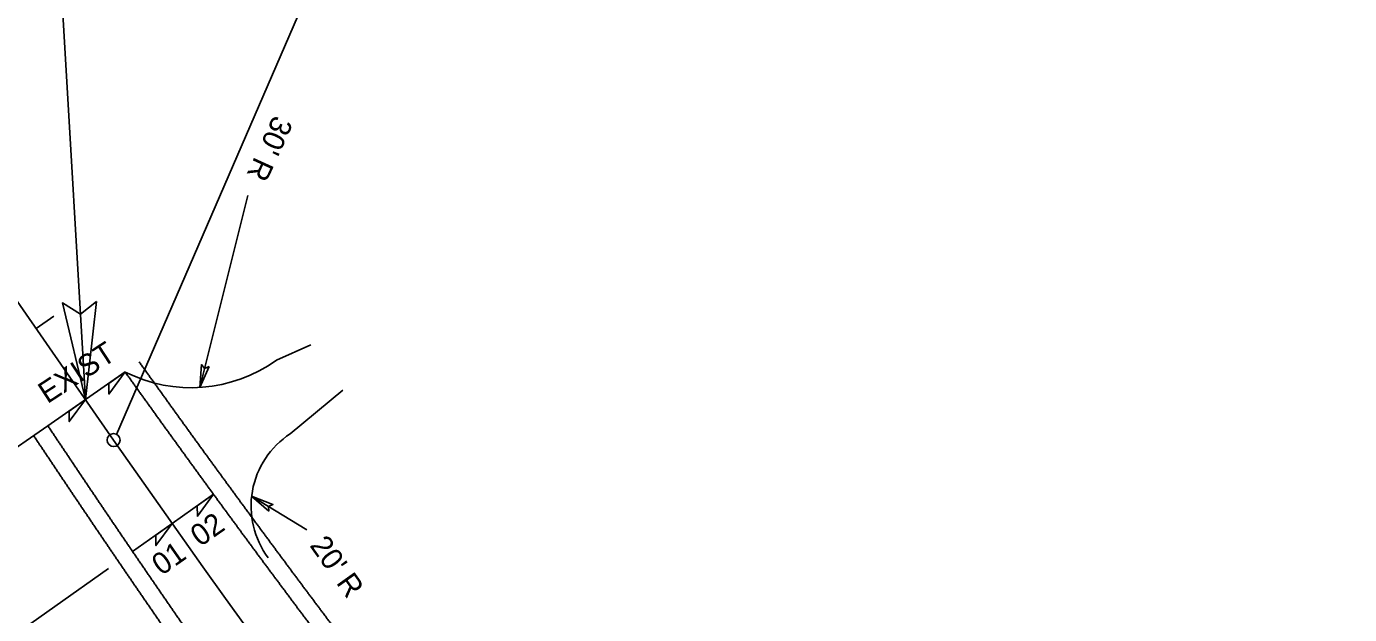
# Model space of a CAD drawing. Extents: x 1778969 to 1790720, y 807089 to 817794.
# Drawn here: x 1781813.6 to 1782119.6, y 815027.8 to 815163.8 of the extents above; entities that cross this region are included whole.
import ezdxf

# ---------------------------------------------------------------- set-up
doc = ezdxf.new("R2010")
doc.units = 0
for name, color, linetype in [('Prop Dimension', 7, 'Continuous'), ('Prop Dimension Text', 7, 'Continuous'), ('Prop EOT', 7, 'Continuous'), ('Prop Horizontal Alignment', 7, 'Continuous'), ('Prop Horizontal Alignment Station Label', 7, 'Continuous'), ('Prop Horizontal Alignment Tick Small', 7, 'Continuous'), ('Prop Paved Shoulder', 7, 'Continuous'), ('Prop Superelevation  Arrow CELL', 7, 'Continuous'), ('Prop Superelevation Label', 7, 'Continuous'), ('Prop Terminator CELL', 7, 'Continuous')]:
    doc.layers.add(name, color=color, linetype=linetype)

msp = doc.modelspace()

# ---------------------------------------------------------------- linework, layer by layer
at = {"layer": 'Prop Dimension'}
for p, q in [((1781864.83, 815124.76), (1781853.71, 815080.33)), ((1781818.55, 815071.48), (1781686.85, 814979.95)), ((1781865.7, 815055.15), (1781878.45, 815047.43)), ((1781832.62, 815038.46), (1781781.53, 815002.33))]:
    msp.add_line(p, q, dxfattribs=at)
at = {"layer": 'Prop EOT'}
for p, q in [((1781871.45, 815086.65), (1781879.41, 815090.18)), ((1781836.43, 815083.91), (1781818.55, 815071.48)), ((1781874.63, 815069.62), (1781886.8, 815079.72))]:
    msp.add_line(p, q, dxfattribs=at)
for centre, radius, start, end in [((1781851.67, 815114.12), 33.85, 243.2689, 305.749), ((1781885.57, 815052.87), 20, 123.1508, 216.6578)]:
    msp.add_arc(centre, radius, start, end, dxfattribs=at)
for points in [[(1781836.43, 815083.91), (1781837, 815083.11), (1781837.58, 815082.32), (1781838.15, 815081.52), (1781838.72, 815080.73), (1781839.29, 815079.93), (1781839.86, 815079.13), (1781840.44, 815078.34), (1781841.01, 815077.54), (1781841.58, 815076.75), (1781842.15, 815075.95), (1781842.72, 815075.16), (1781843.29, 815074.36), (1781843.86, 815073.57), (1781844.43, 815072.78), (1781845, 815071.98), (1781845.57, 815071.19), (1781846.15, 815070.4), (1781846.72, 815069.61), (1781847.29, 815068.82), (1781847.86, 815068.03), (1781848.43, 815067.24), (1781849, 815066.45), (1781849.58, 815065.65), (1781850.15, 815064.86), (1781850.72, 815064.07), (1781851.29, 815063.28), (1781851.87, 815062.5), (1781852.44, 815061.71), (1781853.02, 815060.92), (1781853.59, 815060.13), (1781854.17, 815059.34), (1781854.74, 815058.55), (1781855.31, 815057.76), (1781855.89, 815056.97), (1781856.47, 815056.18), (1781857.04, 815055.4), (1781857.62, 815054.61), (1781858.19, 815053.82), (1781858.77, 815053.03), (1781859.35, 815052.25), (1781859.93, 815051.46), (1781860.5, 815050.67), (1781861.08, 815049.89), (1781861.66, 815049.1), (1781862.24, 815048.32), (1781862.81, 815047.53), (1781863.39, 815046.74), (1781863.97, 815045.96), (1781864.55, 815045.17), (1781865.13, 815044.39), (1781865.71, 815043.6), (1781866.29, 815042.82), (1781866.87, 815042.03), (1781867.45, 815041.25), (1781868.03, 815040.47), (1781868.61, 815039.68), (1781869.2, 815038.9), (1781869.78, 815038.11), (1781870.36, 815037.33), (1781870.94, 815036.55), (1781871.52, 815035.77), (1781872.11, 815034.98), (1781872.69, 815034.2), (1781873.27, 815033.42), (1781873.86, 815032.64), (1781874.44, 815031.85), (1781875.02, 815031.07), (1781875.61, 815030.29), (1781876.19, 815029.51), (1781876.78, 815028.73), (1781877.36, 815027.95), (1781877.95, 815027.17), (1781878.53, 815026.39), (1781879.12, 815025.61)], [(1781818.55, 815071.48), (1781819.1, 815070.67), (1781819.64, 815069.85), (1781820.19, 815069.04), (1781820.73, 815068.22), (1781821.28, 815067.41), (1781821.82, 815066.6), (1781822.37, 815065.78), (1781822.92, 815064.97), (1781823.46, 815064.15), (1781824.01, 815063.34), (1781824.55, 815062.53), (1781825.1, 815061.71), (1781825.65, 815060.89), (1781826.19, 815060.08), (1781826.74, 815059.26), (1781827.29, 815058.45), (1781827.84, 815057.63), (1781828.39, 815056.81), (1781828.94, 815056), (1781829.49, 815055.18), (1781830.04, 815054.37), (1781830.59, 815053.55), (1781831.14, 815052.74), (1781831.69, 815051.92), (1781832.24, 815051.11), (1781832.79, 815050.29), (1781833.34, 815049.48), (1781833.9, 815048.66), (1781834.45, 815047.85), (1781835, 815047.04), (1781835.55, 815046.22), (1781836.11, 815045.41), (1781836.66, 815044.6), (1781837.21, 815043.78), (1781837.77, 815042.97), (1781838.32, 815042.16), (1781838.88, 815041.34), (1781839.43, 815040.53), (1781839.99, 815039.72), (1781840.54, 815038.91), (1781841.1, 815038.1), (1781841.65, 815037.28), (1781842.21, 815036.47), (1781842.77, 815035.66), (1781843.32, 815034.85), (1781843.88, 815034.04), (1781844.44, 815033.23), (1781844.99, 815032.42), (1781845.55, 815031.61), (1781846.11, 815030.8), (1781846.67, 815029.99), (1781847.23, 815029.18), (1781847.79, 815028.37), (1781848.34, 815027.56), (1781848.9, 815026.75), (1781849.46, 815025.94), (1781850.02, 815025.13), (1781850.58, 815024.32), (1781851.14, 815023.52), (1781851.71, 815022.71), (1781852.27, 815021.9), (1781852.83, 815021.09), (1781853.39, 815020.28), (1781853.95, 815019.48), (1781854.51, 815018.67), (1781855.08, 815017.86), (1781855.64, 815017.05), (1781856.2, 815016.25), (1781856.77, 815015.44), (1781857.33, 815014.64), (1781857.89, 815013.83), (1781858.46, 815013.02), (1781859.02, 815012.22), (1781859.59, 815011.41)]]:
    msp.add_spline(points, degree=3, dxfattribs=at)
at = {"layer": 'Prop Horizontal Alignment'}
msp.add_line((1781644.64, 815340.3), (1781833.78, 815068.16), dxfattribs=at)
msp.add_arc((1784215.14, 816723.19), 2900, 214.79915, 237.40395, dxfattribs=at)
at = {"layer": 'Prop Horizontal Alignment Station Label'}
for p, q in [((1781827.26, 815077.53), (1781807.83, 815409.38)), ((1781834.48, 815069.48), (1781911.72, 815248))]:
    msp.add_line(p, q, dxfattribs=at)
msp.add_circle((1781833.78, 815068.16), 1.5, dxfattribs=at)
at = {"layer": 'Prop Horizontal Alignment Tick Small'}
msp.add_line((1781815.85, 815093.96), (1781819.95, 815096.81), dxfattribs=at)
at = {"layer": 'Prop Paved Shoulder'}
for points in [[(1781839.68, 815086.24), (1781840.25, 815085.45), (1781840.83, 815084.65), (1781841.4, 815083.86), (1781841.97, 815083.06), (1781842.54, 815082.26), (1781843.11, 815081.47), (1781843.68, 815080.67), (1781844.26, 815079.88), (1781844.83, 815079.08), (1781845.4, 815078.29), (1781845.97, 815077.49), (1781846.54, 815076.7), (1781847.11, 815075.9), (1781847.68, 815075.11), (1781848.25, 815074.32), (1781848.82, 815073.53), (1781849.39, 815072.74), (1781849.96, 815071.95), (1781850.53, 815071.16), (1781851.1, 815070.37), (1781851.67, 815069.58), (1781852.24, 815068.79), (1781852.82, 815068), (1781853.39, 815067.21), (1781853.96, 815066.42), (1781854.53, 815065.63), (1781855.1, 815064.85), (1781855.68, 815064.06), (1781856.25, 815063.27), (1781856.82, 815062.48), (1781857.4, 815061.69), (1781857.97, 815060.91), (1781858.55, 815060.12), (1781859.12, 815059.33), (1781859.7, 815058.54), (1781860.27, 815057.76), (1781860.85, 815056.97), (1781861.42, 815056.19), (1781862, 815055.4), (1781862.57, 815054.61), (1781863.15, 815053.83), (1781863.73, 815053.04), (1781864.3, 815052.26), (1781864.88, 815051.47), (1781865.46, 815050.69), (1781866.04, 815049.9), (1781866.61, 815049.12), (1781867.19, 815048.33), (1781867.77, 815047.55), (1781868.35, 815046.76), (1781868.93, 815045.98), (1781869.51, 815045.2), (1781870.09, 815044.41), (1781870.67, 815043.63), (1781871.25, 815042.85), (1781871.83, 815042.06), (1781872.41, 815041.28), (1781872.99, 815040.5), (1781873.57, 815039.72), (1781874.15, 815038.94), (1781874.73, 815038.15), (1781875.31, 815037.37), (1781875.9, 815036.59), (1781876.48, 815035.81), (1781877.06, 815035.03), (1781877.64, 815034.25), (1781878.23, 815033.47), (1781878.81, 815032.69), (1781879.4, 815031.91), (1781879.98, 815031.13), (1781880.56, 815030.35), (1781881.15, 815029.57), (1781881.73, 815028.79), (1781882.32, 815028.01)], [(1781815.23, 815069.25), (1781815.77, 815068.44), (1781816.32, 815067.63), (1781816.87, 815066.81), (1781817.41, 815066), (1781817.96, 815065.18), (1781818.5, 815064.37), (1781819.05, 815063.56), (1781819.59, 815062.74), (1781820.14, 815061.93), (1781820.68, 815061.11), (1781821.23, 815060.3), (1781821.78, 815059.48), (1781822.32, 815058.67), (1781822.87, 815057.85), (1781823.42, 815057.03), (1781823.97, 815056.21), (1781824.52, 815055.4), (1781825.07, 815054.58), (1781825.62, 815053.76), (1781826.17, 815052.95), (1781826.72, 815052.13), (1781827.27, 815051.31), (1781827.82, 815050.5), (1781828.38, 815049.68), (1781828.93, 815048.86), (1781829.48, 815048.05), (1781830.03, 815047.23), (1781830.59, 815046.42), (1781831.14, 815045.6), (1781831.69, 815044.79), (1781832.25, 815043.97), (1781832.8, 815043.16), (1781833.35, 815042.34), (1781833.91, 815041.53), (1781834.46, 815040.72), (1781835.02, 815039.9), (1781835.57, 815039.09), (1781836.13, 815038.28), (1781836.68, 815037.46), (1781837.24, 815036.65), (1781837.8, 815035.84), (1781838.35, 815035.02), (1781838.91, 815034.21), (1781839.47, 815033.4), (1781840.02, 815032.59), (1781840.58, 815031.77), (1781841.14, 815030.96), (1781841.7, 815030.15), (1781842.26, 815029.34), (1781842.82, 815028.53), (1781843.37, 815027.72), (1781843.93, 815026.91), (1781844.49, 815026.1), (1781845.05, 815025.29), (1781845.61, 815024.48), (1781846.17, 815023.67), (1781846.74, 815022.86), (1781847.3, 815022.05), (1781847.86, 815021.24), (1781848.42, 815020.43), (1781848.98, 815019.62), (1781849.54, 815018.81), (1781850.11, 815018), (1781850.67, 815017.19), (1781851.23, 815016.38), (1781851.79, 815015.57), (1781852.36, 815014.77), (1781852.92, 815013.96), (1781853.49, 815013.15), (1781854.05, 815012.34), (1781854.62, 815011.54), (1781855.18, 815010.73), (1781855.75, 815009.92), (1781856.31, 815009.12)], [(1781882.32, 815028.01), (1781882.9, 815027.23), (1781883.49, 815026.45), (1781884.07, 815025.67), (1781884.66, 815024.89), (1781885.25, 815024.12), (1781885.83, 815023.34), (1781886.42, 815022.56), (1781887.01, 815021.78), (1781887.59, 815021), (1781888.18, 815020.23), (1781888.77, 815019.45), (1781889.36, 815018.67), (1781889.95, 815017.9), (1781890.54, 815017.12), (1781891.12, 815016.35), (1781891.71, 815015.57), (1781892.3, 815014.79), (1781892.89, 815014.02), (1781893.48, 815013.24), (1781894.07, 815012.47), (1781894.66, 815011.69), (1781895.25, 815010.92), (1781895.84, 815010.14), (1781896.44, 815009.37), (1781897.03, 815008.59), (1781897.62, 815007.82), (1781898.21, 815007.05), (1781898.8, 815006.27), (1781899.4, 815005.5), (1781899.99, 815004.73), (1781900.58, 815003.95), (1781901.17, 815003.18), (1781901.77, 815002.41), (1781902.36, 815001.64), (1781902.96, 815000.87), (1781903.55, 815000.09), (1781904.15, 814999.32), (1781904.74, 814998.55), (1781905.34, 814997.78), (1781905.93, 814997.01), (1781906.53, 814996.24), (1781907.12, 814995.47), (1781907.72, 814994.7), (1781908.31, 814993.93), (1781908.91, 814993.16), (1781909.51, 814992.39), (1781910.11, 814991.62), (1781910.7, 814990.85), (1781911.3, 814990.08), (1781911.9, 814989.31), (1781912.5, 814988.54), (1781913.1, 814987.77), (1781913.69, 814987), (1781914.29, 814986.24), (1781914.89, 814985.47), (1781915.49, 814984.7), (1781916.09, 814983.93), (1781916.69, 814983.16), (1781917.29, 814982.4), (1781917.89, 814981.63), (1781918.49, 814980.86), (1781919.09, 814980.1), (1781919.69, 814979.33), (1781920.3, 814978.57), (1781920.9, 814977.8), (1781921.5, 814977.03), (1781922.1, 814976.27), (1781922.71, 814975.5), (1781923.31, 814974.74), (1781923.91, 814973.97), (1781924.51, 814973.21), (1781925.12, 814972.44), (1781925.72, 814971.68), (1781926.33, 814970.92)]]:
    msp.add_spline(points, degree=3, dxfattribs=at)
at = {"layer": 'Prop Superelevation  Arrow CELL'}
for p, q in [((1781856.88, 815055.61), (1781847.31, 815048.85)), ((1781847.31, 815048.85), (1781838.17, 815042.38))]:
    msp.add_line(p, q, dxfattribs=at)
for points in [[(1781836.43, 815083.91), (1781832.69, 815078.81), (1781832.66, 815081.24)], [(1781827.26, 815077.53), (1781823.52, 815072.44), (1781823.49, 815074.86)], [(1781856.88, 815055.61), (1781853.14, 815050.52), (1781853.11, 815052.94)], [(1781847.31, 815048.85), (1781843.57, 815043.75), (1781843.54, 815046.18)]]:
    msp.add_lwpolyline(points, close=True, dxfattribs=at)
at = {"layer": 'Prop Terminator CELL'}
for points in [[(1781829.81, 815100.22), (1781827.26, 815077.53), (1781821.95, 815099.89), (1781826.11, 815097.25)], [(1781855.84, 815085.15), (1781853.71, 815080.33), (1781854.08, 815085.61), (1781854.82, 815084.75)], [(1781869.66, 815051.69), (1781865.7, 815055.15), (1781870.63, 815053.22), (1781869.58, 815052.78)]]:
    msp.add_lwpolyline(points, close=True, dxfattribs=at)

# ---------------------------------------------------------------- texts
at = {"layer": 'Prop Dimension Text'}
for s, rotation, p in [("30' R", 245.4673, (1781870.84, 815143.53)), ("20' R", 305.4606, (1781878.98, 815043.77))]:
    msp.add_text(s, height=5, rotation=rotation, dxfattribs=at).set_placement(p)
at = {"layer": 'Prop Superelevation Label'}
for s, rotation, p in [('EXIST', 33.1658, (1781818.47, 815076.45)), ('02', 34.9687, (1781853.8, 815043.34)), ('01', 34.9687, (1781844.86, 815036.67))]:
    msp.add_text(s, height=5, rotation=rotation, dxfattribs=at).set_placement(p)

doc.saveas('drawing.dxf')
